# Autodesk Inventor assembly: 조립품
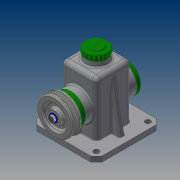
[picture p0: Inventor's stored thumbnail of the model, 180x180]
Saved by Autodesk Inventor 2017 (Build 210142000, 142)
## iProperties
Part Number: 조립품
Material: 일반
Document SubType Name: Assembly
Designer: 20
Author: 20
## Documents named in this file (14)
- C:\Users\20\Desktop\470818V1007\조립품.iam
- C:\Users\20\Desktop\470818V1007\본체.ipt
- C:\Users\20\Desktop\470818V1007\앞커버.ipt
- C:\Users\20\Desktop\470818V1007\뒤커버.ipt
- C:\Users\20\Desktop\470818V1007\오일실 15 25 7.ipt
- C:\Users\20\Desktop\470818V1007\볼트 M4 x 10.ipt
- C:\Users\20\Desktop\470818V1007\베어링 15 x 35 x 11.ipt
- C:\Users\20\Desktop\470818V1007\축.ipt
- C:\Users\20\Desktop\470818V1007\멈춤링 15 x 1.ipt
- C:\Users\20\Desktop\470818V1007\V-벨트풀리.ipt
- C:\Users\20\Desktop\470818V1007\키 5 x 5 x 14.ipt
- C:\Users\20\Desktop\470818V1007\와셔.ipt
- C:\Users\20\Desktop\470818V1007\볼트 M6 x 12.ipt
- C:\Users\20\Desktop\470818V1007\상부캡.ipt
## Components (1 placed, 1 different names)
1. V-벨트풀리:1
